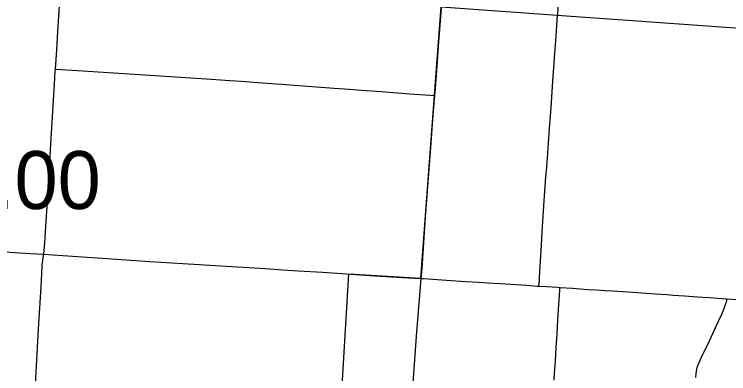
# Model space of a CAD drawing. Extents: x 1815539 to 1947826, y 273303 to 993194.
# Drawn here: x 1848246 to 1861816, y 897220 to 904048 of the extents above; entities that cross this region are included whole.
import ezdxf

# ---------------------------------------------------------------- set-up
doc = ezdxf.new("R2010")
doc.units = 0
for name, color, linetype in [('Default', 7, 'Continuous'), ('GM_X_County_Road', 7, 'Continuous'), ('GM_X_Township', 7, 'Continuous'), ('GM_X_Township_Road', 7, 'Continuous')]:
    doc.layers.add(name, color=color, linetype=linetype)

msp = doc.modelspace()

# ---------------------------------------------------------------- linework, layer by layer
at = {"layer": 'GM_X_County_Road'}
for points in [[(1858565, 904030), (1858567, 904045), (1858584, 904290), (1858607, 904618), (1858637, 905060), (1858651, 905257), (1858662, 905388), (1858673, 905551), (1858688, 905797), (1858702, 905994), (1858746, 906633), (1858768, 906944), (1858785, 907189), (1858796, 907353), (1858803, 907455)], [(1849028, 903004), (1849051, 903376), (1849073, 903720), (1849093, 904015), (1849132, 904620), (1849140, 904747)], [(1856232, 902508), (1856237, 902567), (1856269, 902977), (1856304, 903435), (1856353, 904090), (1856359, 904183)], [(1858212, 898884), (1858214, 898917), (1858231, 899163), (1858248, 899458), (1858261, 899671), (1858275, 899917), (1858313, 900507), (1858345, 900966), (1858358, 901146), (1858377, 901408), (1858411, 901883), (1858428, 902112), (1858441, 902276), (1858454, 902472), (1858476, 902784), (1858493, 903029), (1858508, 903226), (1858530, 903553), (1858543, 903734), (1858565, 904030)], [(1848803, 899489), (1848805, 899500), (1848812, 899560), (1848824, 899707), (1848844, 900018), (1848868, 900395), (1848879, 900591), (1848896, 900853), (1848922, 901263), (1848968, 902000), (1849011, 902721), (1849025, 902966), (1849028, 903004)], [(1855976, 899029), (1855991, 899228), (1856045, 899997), (1856058, 900193), (1856127, 901109), (1856159, 901518), (1856179, 901779), (1856205, 902139), (1856232, 902508)], [(1848439, 893732), (1848441, 893763), (1848490, 894516), (1848516, 894909), (1848524, 895057), (1848530, 895171), (1848556, 895564), (1848586, 896023), (1848613, 896465), (1848628, 896694), (1848647, 897022), (1848665, 897366), (1848707, 898070), (1848754, 898873), (1848774, 899250), (1848778, 899288), (1848782, 899332), (1848785, 899370), (1848787, 899396), (1848798, 899459), (1848803, 899489)], [(1854556, 899117), (1854822, 899099), (1855099, 899082), (1855621, 899050), (1855976, 899029)], [(1855588, 893286), (1855600, 893503), (1855626, 893929), (1855679, 894763), (1855701, 895107), (1855747, 895909), (1855791, 896596), (1855857, 897578), (1855893, 898019), (1855957, 898787), (1855976, 899029)], [(1855976, 899029), (1856016, 899027), (1856457, 898998), (1856818, 898973), (1857063, 898958), (1857243, 898947), (1857472, 898934), (1857669, 898922), (1857980, 898900), (1858176, 898886), (1858212, 898884)], [(1858212, 898884), (1858356, 898874), (1858569, 898863), (1858612, 898860)], [(1858500, 897098), (1858509, 897229), (1858523, 897458), (1858540, 897720), (1858551, 897883), (1858557, 897981), (1858573, 898243), (1858591, 898538), (1858601, 898701), (1858609, 898816), (1858612, 898860)], [(1858612, 898860), (1858847, 898844), (1859142, 898822), (1859305, 898811), (1859469, 898801), (1859600, 898793), (1859911, 898774), (1860418, 898739), (1860647, 898723), (1860762, 898715), (1860975, 898700), (1861138, 898688), (1861318, 898674), (1861449, 898666), (1861694, 898648), (1861787, 898642)], [(1861787, 898642), (1861890, 898635), (1861972, 898630), (1862120, 898619), (1862299, 898607), (1862479, 898594), (1862645, 898582)]]:
    msp.add_lwpolyline(points, dxfattribs=at)
at = {"layer": 'GM_X_Township'}
msp.add_lwpolyline([(1853740, 885139), (1853912, 887891), (1854256, 893376), (1854601, 899118), (1855968, 899037), (1856227, 902512), (1856354, 904189), (1858556, 904033), (1863007, 903717), (1863265, 907135), (1863306, 907714), (1863375, 908580), (1863406, 908966), (1863544, 910397), (1864246, 910459), (1864806, 910520), (1866935, 910696), (1872022, 911301), (1871903, 909711), (1873264, 909583), (1874571, 909455), (1879532, 909040), (1882082, 908847)], dxfattribs=at)
at = {"layer": 'GM_X_Township_Road'}
for points in [[(1849028, 903004), (1849043, 903003), (1849446, 902978), (1850036, 902940), (1850723, 902897), (1851116, 902873), (1851983, 902815), (1852342, 902790), (1852555, 902776), (1853045, 902740), (1853324, 902721), (1853977, 902672), (1854157, 902658), (1854320, 902645), (1854615, 902625), (1854843, 902609), (1855219, 902583), (1855759, 902540), (1856232, 902508)], [(1845066, 899723), (1845147, 899721), (1845255, 899713), (1845402, 899702), (1845680, 899685), (1846024, 899665), (1846401, 899642), (1847023, 899602), (1847498, 899572), (1847957, 899544), (1848547, 899506), (1848803, 899489)], [(1848803, 899489), (1849169, 899464), (1849447, 899446), (1849627, 899435), (1849922, 899414), (1850823, 899354), (1851445, 899313), (1852166, 899269), (1852477, 899250), (1852706, 899237), (1853017, 899216), (1853344, 899193), (1853639, 899176), (1854098, 899147), (1854556, 899117)], [(1861192, 897151), (1861197, 897223), (1861203, 897271), (1861210, 897305), (1861218, 897340), (1861234, 897387), (1861300, 897536), (1861442, 897833), (1861519, 897996), (1861617, 898204), (1861687, 898352), (1861731, 898458), (1861763, 898551), (1861772, 898580), (1861780, 898614), (1861787, 898642)]]:
    msp.add_lwpolyline(points, dxfattribs=at)

# ---------------------------------------------------------------- texts
at = {"layer": 'Default'}
msp.add_text('4.00', height=1100, dxfattribs=at).set_placement((1847025, 900349))

doc.saveas('drawing.dxf')
